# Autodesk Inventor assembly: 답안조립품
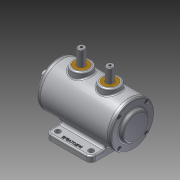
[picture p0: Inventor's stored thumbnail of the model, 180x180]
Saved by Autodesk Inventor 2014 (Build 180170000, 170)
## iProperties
Created: 2014-12
Part Number: 답안조립품
Document SubType Name: Assembly
Designer: Owner
Author: Owner
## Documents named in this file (10)
- C:\Users\Owner\Desktop\441223V1016\답안조립품.iam
- C:\Users\Owner\Desktop\441223V1016\본체.ipt
- C:\Users\Owner\Desktop\441223V1016\M4-소켓머리.ipt
- C:\Users\Owner\Desktop\441223V1016\뒷커버.ipt
- C:\Users\Owner\Desktop\441223V1016\베어링 6203.ipt
- C:\Users\Owner\Desktop\441223V1016\부시.ipt
- C:\Users\Owner\Desktop\441223V1016\슬라이더.ipt
- C:\Users\Owner\Desktop\441223V1016\앞커버.ipt
- C:\Users\Owner\Desktop\441223V1016\오일실.ipt
- C:\Users\Owner\Desktop\441223V1016\축.ipt
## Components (11 placed, 3 different names)
1. 7-베어링 6203:1
2. 8-오일실:1
3. 7-베어링 6203:2
4. 9-M4-소켓머리:2
5. 9-M4-소켓머리:3
6. 9-M4-소켓머리:4
7. 9-M4-소켓머리:5
8. 9-M4-소켓머리:1
9. 9-M4-소켓머리:6
10. 9-M4-소켓머리:7
11. 9-M4-소켓머리:8
